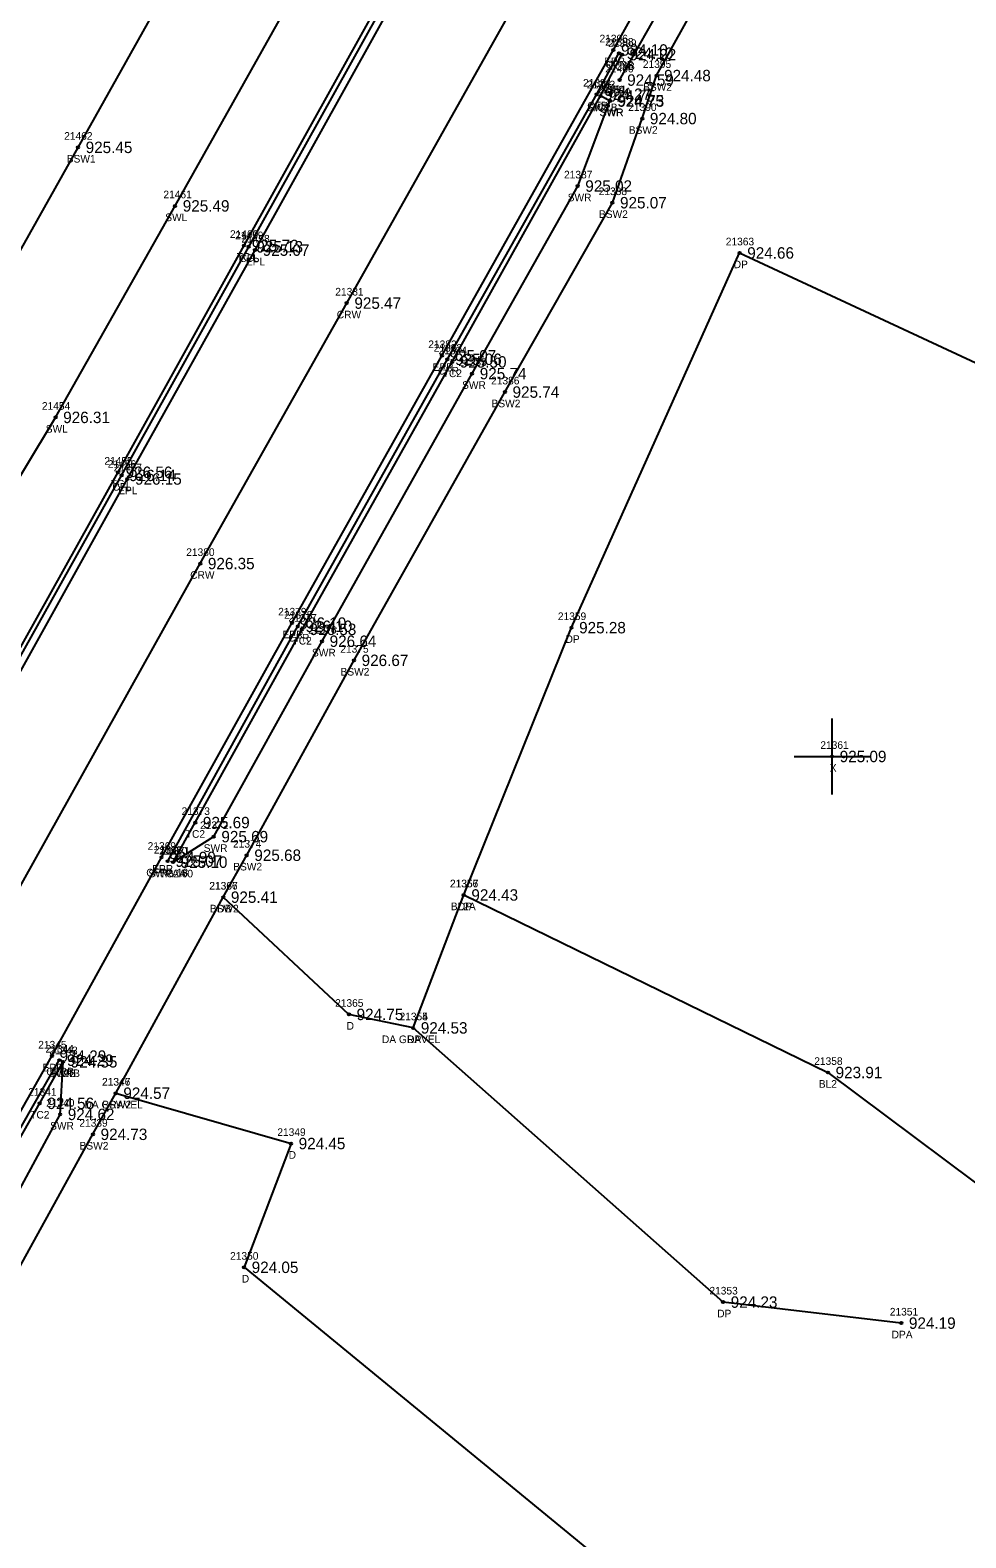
# Model space of a CAD drawing. Extents: x 1576181 to 1577685, y 1099396 to 1101490.
# Drawn here: x 1576951.6 to 1577074.4, y 1100432.1 to 1100630.2 of the extents above; entities that cross this region are included whole.
import ezdxf

# ---------------------------------------------------------------- set-up
doc = ezdxf.new("R2010")
doc.units = 0
for name, color, linetype in [('RD_DTM_BkLn1', 7, 'Continuous'), ('RD_DTM_BkLn2', 7, 'Continuous'), ('RD_DTM_BkLn_txCode', 7, 'Continuous'), ('RD_EX_Conc', 7, 'Continuous'), ('RD_EX_Conc_txCode', 7, 'Continuous'), ('RD_EX_Driveway', 7, 'Continuous'), ('RD_EX_Driveway_txCode', 7, 'Continuous'), ('RD_EX_Misc', 7, 'Continuous'), ('RD_EX_Misc_txCode', 7, 'Continuous'), ('RD_EX_Road', 7, 'Continuous'), ('RD_EX_Road_txCode', 7, 'Continuous'), ('RD_EX_TX_Conc_ELEV', 7, 'Continuous'), ('RD_EX_TX_Driveway_ELEV', 7, 'Continuous'), ('RD_EX_TX_Misc_ELEV', 7, 'Continuous'), ('RD_EX_TX_Road_ELEV', 7, 'Continuous'), ('RD_HC_Survey_ELEV', 7, 'Continuous'), ('RD_HC_Survey_txCode', 7, 'Continuous'), ('RD_SMD_Locator', 7, 'Continuous')]:
    doc.layers.add(name, color=color, linetype=linetype)

msp = doc.modelspace()

# ---------------------------------------------------------------- linework, layer by layer
at = {"layer": 'RD_DTM_BkLn1'}
msp.add_line((1577028.95, 1100623.63), (1577050.18, 1100661.17), dxfattribs=at)
for points in [[(1576908.25, 1100441.74), (1576920.44, 1100463.64), (1576944.47, 1100507.42), (1576973.89, 1100560.12), (1576993.13, 1100594.33), (1577014.77, 1100632.79), (1577042.14, 1100681.68), (1577066.82, 1100725.12), (1577089.75, 1100766.04), (1577111.87, 1100810.02), (1577132.74, 1100857.48), (1577152.58, 1100903.02), (1577172.32, 1100949.02), (1577191.93, 1100994.6), (1577211.77, 1101040.76), (1577222.24, 1101065.99), (1577231.17, 1101086.4), (1577251.41, 1101132.37), (1577271.56, 1101178.18), (1577291.61, 1101224.24), (1577311.77, 1101270.05), (1577333.79, 1101320.46), (1577355.93, 1101371.29), (1577365.01, 1101392.03)], [(1577008.49, 1100516.59), (1577056.32, 1100493.27), (1577083.15, 1100473.22)]]:
    msp.add_lwpolyline(points, dxfattribs=at)
at = {"layer": 'RD_DTM_BkLn2'}
for points in [[(1576914.94, 1100485.67), (1576931.23, 1100514.99), (1576963.09, 1100572.11), (1576979.65, 1100601.9), (1577003.92, 1100645.56), (1577028.33, 1100689.49), (1577054.68, 1100736.79), (1577056.96, 1100744.82), (1577057.69, 1100753.73), (1577056.33, 1100759.1), (1577053.62, 1100754.24)], [(1576970.32, 1100520.9), (1576973.24, 1100526.1), (1576987.25, 1100551.48), (1577006.97, 1100586.61), (1577026.45, 1100621.54), (1577029.26, 1100626.97)], [(1576941.06, 1100468.55), (1576952.81, 1100489.22), (1576955.87, 1100494.67)]]:
    msp.add_lwpolyline(points, dxfattribs=at)
at = {"layer": 'RD_EX_Conc'}
msp.add_line((1576940.49, 1100468.87), (1576955.37, 1100494.89), dxfattribs=at)
for points in [[(1576915.51, 1100485.43), (1576931.67, 1100514.72), (1576963.55, 1100571.7), (1576980.25, 1100601.73), (1577004.87, 1100645.93), (1577028.8, 1100689.21), (1577055.24, 1100736.45), (1577057.45, 1100744.79), (1577058.3, 1100753.83), (1577056.52, 1100760.31), (1577053.21, 1100754.37)], [(1576891.15, 1100493), (1576919.81, 1100523.92), (1576927.44, 1100533.74), (1576954.89, 1100579.32), (1576970.59, 1100607.1), (1576994.86, 1100650.35), (1577020.05, 1100695.25), (1577043.02, 1100736.52), (1577053.21, 1100754.37)], [(1576877.92, 1100500.23), (1576907.33, 1100532.14), (1576916.05, 1100543.22), (1576941.93, 1100586.45), (1576957.84, 1100614.79), (1576982.46, 1100658.75), (1577007.42, 1100703.25), (1577021.88, 1100729.08)], [(1576925.28, 1100434.6), (1576931.32, 1100441.65), (1576943.72, 1100456.06), (1576959.8, 1100485.15), (1576962.79, 1100490.55), (1576976.91, 1100516.3), (1576979.99, 1100521.81), (1576994.08, 1100547.41), (1577013.9, 1100582.65), (1577028.01, 1100607.52), (1577031.93, 1100618.57), (1577033.8, 1100624.22), (1577052.4, 1100657.66), (1577055.15, 1100662.64), (1577085.17, 1100716.01)], [(1576969.62, 1100521.03), (1576986.7, 1100551.88), (1577006.34, 1100586.95), (1577025.95, 1100621.77), (1577028.87, 1100627.15)], [(1576970.32, 1100520.9), (1576975.66, 1100524.25), (1576989.88, 1100549.92), (1577009.59, 1100585.07), (1577023.45, 1100609.71), (1577027.68, 1100620.87), (1577027.64, 1100620.91), (1577026.45, 1100621.54)], [(1576944.24, 1100467), (1576955.49, 1100487.77), (1576955.87, 1100494.67)]]:
    msp.add_lwpolyline(points, dxfattribs=at)
at = {"layer": 'RD_EX_Driveway'}
for points in [[(1577065.95, 1100460.35), (1577042.55, 1100463.11), (1577001.85, 1100499.13), (1577008.49, 1100516.59), (1577022.64, 1100551.7), (1577044.72, 1100600.92), (1577090.31, 1100579.68)], [(1577001.85, 1100499.13), (1576993.42, 1100500.9), (1576976.91, 1100516.3)], [(1576962.79, 1100490.55), (1576985.81, 1100483.94), (1576979.64, 1100467.68), (1577039.26, 1100418.73)]]:
    msp.add_lwpolyline(points, dxfattribs=at)
at = {"layer": 'RD_EX_Misc'}
for p, q in [((1577056.86, 1100529.78), (1577056.86, 1100539.78)), ((1577051.86, 1100534.78), (1577061.86, 1100534.78))]:
    msp.add_line(p, q, dxfattribs=at)
at = {"layer": 'RD_EX_Road'}
for points in [[(1576898.13, 1100449.6), (1576900.3, 1100453.32), (1576908.44, 1100470.19), (1576911.63, 1100476.81), (1576915.14, 1100482.86), (1576932.49, 1100514.03), (1576964.32, 1100571.23), (1576981.09, 1100601.29), (1577005.14, 1100644.55), (1577029.51, 1100688.7), (1577055.93, 1100735.94), (1577058.21, 1100744.65), (1577059.15, 1100754.07), (1577057.45, 1100760.72), (1577053.13, 1100767.88), (1577044.53, 1100776.69), (1577044.53, 1100776.69), (1577000.54, 1100813.12)], [(1576918.43, 1100436.45), (1576919.69, 1100438.1), (1576919.21, 1100438.45), (1576924.62, 1100446.41), (1576935.15, 1100461.4), (1576954.41, 1100495.42), (1576968.8, 1100521.52), (1576985.92, 1100552.3), (1577005.62, 1100587.42), (1577028.14, 1100627.58), (1577046.67, 1100660.87), (1577078.76, 1100718.33)]]:
    msp.add_lwpolyline(points, dxfattribs=at)
at = {"layer": 'RD_SMD_Locator'}
for centre in [(1577028.14, 1100627.58), (1577028.87, 1100627.15), (1577029.26, 1100626.97), (1577028.95, 1100623.63), (1577033.8, 1100624.22), (1577025.95, 1100621.77), (1577026.45, 1100621.54), (1577026.45, 1100621.54), (1577027.64, 1100620.91), (1577027.68, 1100620.87), (1577031.93, 1100618.57), (1576957.84, 1100614.79), (1577023.45, 1100609.71), (1577028.01, 1100607.52), (1576970.59, 1100607.1), (1576979.65, 1100601.9), (1576980.25, 1100601.73), (1576981.09, 1100601.29), (1577044.72, 1100600.92), (1576993.13, 1100594.33), (1577005.62, 1100587.42), (1577006.34, 1100586.95), (1577006.97, 1100586.61), (1577009.59, 1100585.07), (1577013.9, 1100582.65), (1576954.89, 1100579.32), (1576963.09, 1100572.11), (1576963.55, 1100571.7), (1576964.32, 1100571.23), (1576973.89, 1100560.12), (1576985.92, 1100552.3), (1576986.7, 1100551.88), (1576987.25, 1100551.48), (1577022.64, 1100551.7), (1576989.88, 1100549.92), (1576994.08, 1100547.41), (1577056.86, 1100534.78), (1576973.24, 1100526.1), (1576975.66, 1100524.25), (1576968.8, 1100521.52), (1576969.62, 1100521.03), (1576970.32, 1100520.9), (1576970.32, 1100520.9), (1576979.99, 1100521.81), (1577008.49, 1100516.59), (1577008.49, 1100516.59), (1576976.91, 1100516.3), (1576976.91, 1100516.3), (1576993.42, 1100500.9), (1577001.85, 1100499.13), (1577001.85, 1100499.13), (1576954.41, 1100495.42), (1576955.37, 1100494.89), (1576955.87, 1100494.67), (1576955.87, 1100494.67), (1577056.32, 1100493.27), (1576952.81, 1100489.22), (1576962.79, 1100490.55), (1576962.79, 1100490.55), (1576955.49, 1100487.77), (1576959.8, 1100485.15), (1576985.81, 1100483.94), (1576979.64, 1100467.68), (1577042.55, 1100463.11), (1577065.95, 1100460.35)]:
    msp.add_circle(centre, 0.15, dxfattribs=at)

# ---------------------------------------------------------------- texts
at = {"layer": 'RD_DTM_BkLn_txCode'}
for s, p in [('21400', (1577027.08, 1100624.63)), ('BL2A', (1577027.26, 1100621.63)), ('21357', (1577006.69, 1100517.59)), ('BL2A', (1577006.79, 1100514.59)), ('21358', (1577054.52, 1100494.27)), ('BL2', (1577055.11, 1100491.27))]:
    msp.add_text(s, height=1, dxfattribs=at).set_placement(p)
at = {"layer": 'RD_EX_Conc_txCode'}
for s, p in [('21398', (1577027.07, 1100628.15)), ('21399', (1577027.47, 1100627.97)), ('CFRB', (1577027.17, 1100625.15)), ('TC2B', (1577027.54, 1100624.97)), ('21395', (1577032.01, 1100625.22)), ('21394', (1577024.16, 1100622.77)), ('21392', (1577024.66, 1100622.54)), ('21393', (1577024.66, 1100622.54)), ('21389', (1577025.89, 1100621.87)), ('21391', (1577026.13, 1100621.91)), ('BSW2', (1577032.04, 1100622.22)), ('SWRB', (1577024.67, 1100619.54)), ('CFR', (1577024.73, 1100619.77)), ('TC2', (1577025.21, 1100619.54)), ('SWR', (1577026.32, 1100618.91)), ('SWR', (1577026.37, 1100618.87)), ('21390', (1577030.09, 1100619.57)), ('BSW2', (1577030.16, 1100616.57)), ('21462', (1576956.02, 1100615.79)), ('BSW1', (1576956.36, 1100612.79)), ('21387', (1577021.66, 1100610.71)), ('21461', (1576969.05, 1100608.1)), ('SWR', (1577022.14, 1100607.71)), ('21388', (1577026.21, 1100608.52)), ('SWL', (1576969.29, 1100605.1)), ('BSW2', (1577026.25, 1100605.52)), ('21460', (1576977.79, 1100602.9)), ('21459', (1576978.46, 1100602.73)), ('TC1', (1576978.69, 1100599.9)), ('CFL', (1576979.05, 1100599.73)), ('21383', (1577004.55, 1100587.95)), ('21384', (1577005.18, 1100587.61)), ('CFR', (1577005.11, 1100584.95)), ('21385', (1577007.79, 1100586.07)), ('TC2', (1577005.73, 1100584.61)), ('SWR', (1577008.27, 1100583.07)), ('21386', (1577012.08, 1100583.65)), ('21454', (1576953.09, 1100580.32)), ('BSW2', (1577012.14, 1100580.65)), ('SWL', (1576953.6, 1100577.32)), ('21455', (1576961.3, 1100573.11)), ('21456', (1576961.74, 1100572.7)), ('TC1', (1576962.13, 1100570.11)), ('CFL', (1576962.35, 1100569.7)), ('21378', (1576984.9, 1100552.88)), ('21377', (1576985.46, 1100552.48)), ('CFR', (1576985.47, 1100549.88)), ('TC2', (1576986.01, 1100549.48)), ('21376', (1576988.06, 1100550.92)), ('SWR', (1576988.56, 1100547.92)), ('21375', (1576992.28, 1100548.41)), ('BSW2', (1576992.31, 1100545.41)), ('21373', (1576971.44, 1100527.1)), ('TC2', (1576971.99, 1100524.1)), ('21372', (1576973.86, 1100525.25)), ('21368', (1576967.8, 1100522.03)), ('21370', (1576968.49, 1100521.9)), ('21371', (1576968.81, 1100521.9)), ('SWR', (1576974.34, 1100522.25)), ('21374', (1576978.19, 1100522.81)), ('BSW2', (1576978.22, 1100519.81)), ('CFRA 18', (1576966.8, 1100519.03)), ('SWRA 60', (1576967.07, 1100518.9)), ('TC2A', (1576968.59, 1100518.9)), ('21366', (1576975.07, 1100517.3)), ('BSW2', (1576975.15, 1100514.3)), ('21344', (1576953.57, 1100495.89)), ('21342', (1576954.07, 1100495.67)), ('21343', (1576954.07, 1100495.67)), ('CFRB', (1576953.67, 1100492.89)), ('SWRB', (1576954.08, 1100492.67)), ('TC2B', (1576954.15, 1100492.67)), ('21341', (1576951.3, 1100490.22)), ('21346', (1576960.98, 1100491.55)), ('21340', (1576953.65, 1100488.77)), ('BSW2', (1576961.03, 1100488.55)), ('TC2', (1576951.56, 1100487.22)), ('21339', (1576958.01, 1100486.15)), ('SWR', (1576954.17, 1100485.77)), ('BSW2', (1576958.04, 1100483.15))]:
    msp.add_text(s, height=1, dxfattribs=at).set_placement(p)
at = {"layer": 'RD_EX_Driveway_txCode'}
for s, p in [('21363', (1577042.9, 1100601.92)), ('DP', (1577043.94, 1100598.92)), ('21359', (1577020.85, 1100552.7)), ('DP', (1577021.86, 1100549.7)), ('21356', (1577006.67, 1100517.59)), ('21367', (1576975.09, 1100517.3)), ('DB', (1576976.13, 1100514.3)), ('DP', (1577007.71, 1100514.59)), ('21365', (1576991.6, 1100501.9)), ('21354', (1577000.06, 1100500.13)), ('21355', (1577000.06, 1100500.13)), ('D', (1576993.11, 1100498.9)), ('DA GRAVEL', (1576997.75, 1100497.13)), ('DP', (1577001.07, 1100497.13)), ('21347', (1576961, 1100491.55)), ('DA GRAVEL', (1576958.69, 1100488.55)), ('21349', (1576984.01, 1100484.94)), ('D', (1576985.5, 1100481.94)), ('21350', (1576977.81, 1100468.68)), ('D', (1576979.34, 1100465.68)), ('21353', (1577040.75, 1100464.11)), ('DP', (1577041.77, 1100461.11)), ('21351', (1577064.44, 1100461.35)), ('DPA', (1577064.68, 1100458.35))]:
    msp.add_text(s, height=1, dxfattribs=at).set_placement(p)
at = {"layer": 'RD_EX_Misc_txCode'}
for s, p in [('21361', (1577055.32, 1100535.78)), ('X', (1577056.55, 1100532.78))]:
    msp.add_text(s, height=1, dxfattribs=at).set_placement(p)
at = {"layer": 'RD_EX_Road_txCode'}
for s, p in [('21396', (1577026.32, 1100628.58)), ('EPR', (1577026.91, 1100625.58)), ('21458', (1576979.29, 1100602.29)), ('EPL', (1576979.88, 1100599.29)), ('21382', (1577003.83, 1100588.42)), ('EPR', (1577004.4, 1100585.42)), ('21457', (1576962.52, 1100572.23)), ('EPL', (1576963.11, 1100569.23)), ('21379', (1576984.12, 1100553.3)), ('EPR', (1576984.69, 1100550.3)), ('21369', (1576966.98, 1100522.52)), ('EPR', (1576967.57, 1100519.52)), ('21345', (1576952.61, 1100496.42)), ('EPR', (1576953.18, 1100493.42))]:
    msp.add_text(s, height=1, dxfattribs=at).set_placement(p)
at = {"layer": 'RD_EX_TX_Conc_ELEV'}
for s, p in [('924.10', (1577029.87, 1100626.4)), ('924.22', (1577030.26, 1100626.22)), ('924.48', (1577034.8, 1100623.47)), ('924.27', (1577026.95, 1100621.02)), ('924.75', (1577027.45, 1100620.79)), ('924.75', (1577027.45, 1100620.79)), ('924.75', (1577028.64, 1100620.16)), ('924.73', (1577028.68, 1100620.12)), ('924.80', (1577032.93, 1100617.82)), ('925.45', (1576958.84, 1100614.04)), ('925.02', (1577024.45, 1100608.96)), ('925.49', (1576971.59, 1100606.35)), ('925.07', (1577029.01, 1100606.77)), ('925.72', (1576980.65, 1100601.15)), ('925.13', (1576981.25, 1100600.98)), ('925.06', (1577007.34, 1100586.2)), ('925.50', (1577007.97, 1100585.86)), ('925.74', (1577010.59, 1100584.32)), ('925.74', (1577014.9, 1100581.9)), ('926.31', (1576955.89, 1100578.57)), ('926.56', (1576964.09, 1100571.36)), ('926.14', (1576964.55, 1100570.95)), ('926.10', (1576987.7, 1100551.13)), ('926.53', (1576988.25, 1100550.73)), ('926.64', (1576990.88, 1100549.17)), ('926.67', (1576995.08, 1100546.66)), ('925.69', (1576974.24, 1100525.35)), ('925.69', (1576976.66, 1100523.5)), ('925.68', (1576980.99, 1100521.06)), ('925.07', (1576970.62, 1100520.28)), ('925.10', (1576971.32, 1100520.15)), ('925.10', (1576971.32, 1100520.15)), ('925.41', (1576977.91, 1100515.55)), ('924.29', (1576956.37, 1100494.14)), ('924.35', (1576956.87, 1100493.92)), ('924.35', (1576956.87, 1100493.92)), ('924.57', (1576963.79, 1100489.8)), ('924.56', (1576953.81, 1100488.47)), ('924.62', (1576956.49, 1100487.02)), ('924.73', (1576960.8, 1100484.4))]:
    msp.add_text(s, height=1.5, dxfattribs=at).set_placement(p)
at = {"layer": 'RD_EX_TX_Driveway_ELEV'}
for s, p in [('924.66', (1577045.72, 1100600.17)), ('925.28', (1577023.64, 1100550.95)), ('925.41', (1576977.91, 1100515.55)), ('924.43', (1577009.49, 1100515.84)), ('924.75', (1576994.42, 1100500.15)), ('924.53', (1577002.85, 1100498.38)), ('924.53', (1577002.85, 1100498.38)), ('924.57', (1576963.79, 1100489.8)), ('924.45', (1576986.81, 1100483.19)), ('924.05', (1576980.64, 1100466.93)), ('924.23', (1577043.55, 1100462.36)), ('924.19', (1577066.95, 1100459.6))]:
    msp.add_text(s, height=1.5, dxfattribs=at).set_placement(p)
at = {"layer": 'RD_EX_TX_Misc_ELEV'}
for s, p in [('924.59', (1577029.95, 1100622.88)), ('925.09', (1577057.86, 1100534.03)), ('924.43', (1577009.49, 1100515.84)), ('923.91', (1577057.32, 1100492.52))]:
    msp.add_text(s, height=1.5, dxfattribs=at).set_placement(p)
at = {"layer": 'RD_EX_TX_Road_ELEV'}
for s, p in [('924.10', (1577029.14, 1100626.83)), ('925.07', (1576982.09, 1100600.54)), ('925.07', (1577006.62, 1100586.67)), ('926.15', (1576965.32, 1100570.48)), ('926.10', (1576986.92, 1100551.55)), ('924.99', (1576969.8, 1100520.77)), ('924.29', (1576955.41, 1100494.67))]:
    msp.add_text(s, height=1.5, dxfattribs=at).set_placement(p)
at = {"layer": 'RD_HC_Survey_ELEV'}
for s, p in [('925.47', (1576994.13, 1100593.58)), ('926.35', (1576974.89, 1100559.37))]:
    msp.add_text(s, height=1.5, dxfattribs=at).set_placement(p)
at = {"layer": 'RD_HC_Survey_txCode'}
for s, p in [('21381', (1576991.62, 1100595.33)), ('CRW', (1576991.82, 1100592.33)), ('21380', (1576972.05, 1100561.12)), ('CRW', (1576972.57, 1100558.12))]:
    msp.add_text(s, height=1, dxfattribs=at).set_placement(p)

doc.saveas('drawing.dxf')
